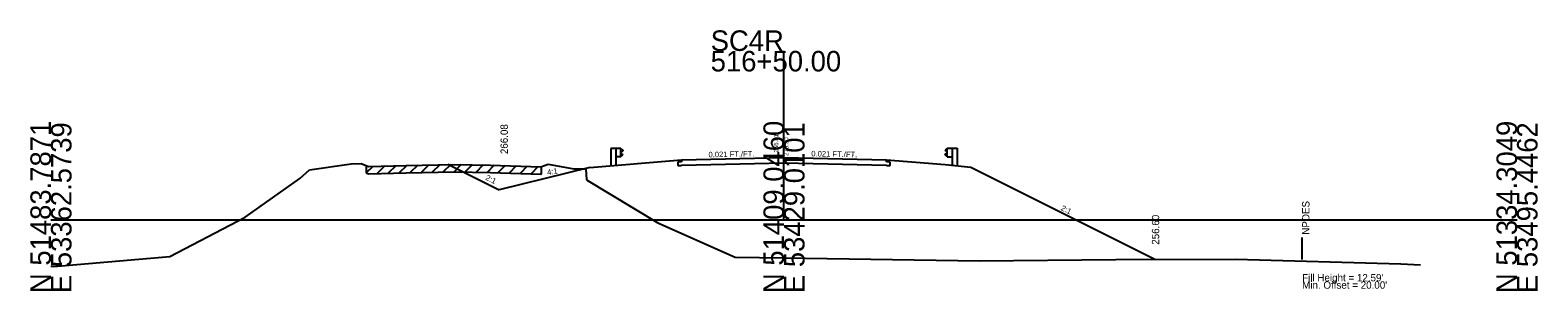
# Model space of a CAD drawing. Extents: x 7498 to 13027, y 90095 to 109625.
# Drawn here: x 8521.2 to 8726.8, y 106595.5 to 106631.1 of the extents above; entities that cross this region are included whole.
import ezdxf

# ---------------------------------------------------------------- set-up
doc = ezdxf.new("R2010")
doc.units = 0
for name, color, linetype in [('Level 10', 7, 'Continuous'), ('Level 11', 7, 'Continuous'), ('Level 12', 7, 'Continuous'), ('Level 24', 7, 'Continuous'), ('Level 32', 7, 'Continuous'), ('Level 33', 7, 'Continuous'), ('Level 50', 7, 'Continuous'), ('Level 55', 7, 'Continuous'), ('Level 59', 7, 'Continuous'), ('Level 6', 7, 'Continuous'), ('Level 60', 7, 'Continuous'), ('Level 61', 7, 'Continuous'), ('Level 63', 7, 'Continuous'), ('Level 7', 7, 'Continuous')]:
    doc.layers.add(name, color=color, linetype=linetype)

msp = doc.modelspace()

# ---------------------------------------------------------------- linework, layer by layer
at = {"layer": 'Level 11'}
for p, q in [((8609.99, 106613.07), (8609.49, 106613.05)), ((8609.49, 106613.05), (8609.49, 106612.57)), ((8609.99, 106613.37), (8609.99, 106613.07)), ((8637.99, 106613.07), (8637.99, 106613.37)), ((8638.49, 106613.05), (8637.99, 106613.07)), ((8638.49, 106612.57), (8638.49, 106613.05)), ((8609.49, 106612.57), (8609.99, 106612.59)), ((8637.99, 106612.59), (8638.49, 106612.57))]:
    msp.add_line(p, q, dxfattribs=at)
at = {"layer": 'Level 12'}
for p, q in [((8623.99, 106612.88), (8609.99, 106612.59)), ((8637.99, 106612.59), (8623.99, 106612.88))]:
    msp.add_line(p, q, dxfattribs=at)
at = {"layer": 'Level 24'}
for p, q in [((8600.38, 106614.92), (8600.38, 106612.51)), ((8601.05, 106614.92), (8600.38, 106614.92)), ((8601.72, 106614.92), (8601.05, 106614.92)), ((8601.05, 106614.92), (8601.05, 106612.57)), ((8601.72, 106613.75), (8601.05, 106613.75)), ((8601.72, 106613.75), (8601.72, 106614.92)), ((8601.72, 106614.85), (8601.99, 106614.65)), ((8601.99, 106614.6), (8601.72, 106614.4)), ((8601.99, 106614.07), (8601.72, 106614.27)), ((8601.72, 106613.82), (8601.99, 106614.02)), ((8601.99, 106614.65), (8601.99, 106614.6)), ((8601.99, 106614.02), (8601.99, 106614.07)), ((8646.26, 106614.88), (8645.99, 106614.68)), ((8645.99, 106614.68), (8645.99, 106614.63)), ((8645.99, 106614.63), (8646.26, 106614.43)), ((8645.99, 106614.1), (8646.26, 106614.3)), ((8645.99, 106614.05), (8645.99, 106614.1)), ((8646.26, 106613.85), (8645.99, 106614.05)), ((8646.26, 106613.78), (8646.26, 106614.95)), ((8646.26, 106614.95), (8646.93, 106614.95)), ((8646.26, 106613.78), (8646.93, 106613.78)), ((8646.93, 106614.95), (8646.93, 106612.6)), ((8646.93, 106614.95), (8647.6, 106614.95)), ((8647.6, 106614.95), (8647.6, 106612.54))]:
    msp.add_line(p, q, dxfattribs=at)
at = {"layer": 'Level 55'}
msp.add_line((8694.68, 106599.76), (8694.68, 106602.76), dxfattribs=at)
at = {"layer": 'Level 59'}
for p, q in [((8609.99, 106613.37), (8623.99, 106613.66)), ((8623.99, 106613.66), (8637.99, 106613.37))]:
    msp.add_line(p, q, dxfattribs=at)
at = {"layer": 'Level 6'}
for p, q in [((8597.49, 106612.32), (8609.99, 106613.37)), ((8637.99, 106613.37), (8645.99, 106612.7)), ((8645.99, 106612.7), (8649.49, 106612.35))]:
    msp.add_line(p, q, dxfattribs=at)
at = {"layer": 'Level 60'}
for p, q in [((8557.93, 106610.79), (8559.24, 106611.97)), ((8559.24, 106611.97), (8564.94, 106612.82)), ((8564.94, 106612.82), (8566.3, 106612.84)), ((8566.3, 106612.84), (8567.29, 106612.45)), ((8567.29, 106612.45), (8572.44, 106612.59)), ((8572.44, 106612.59), (8578.99, 106612.73)), ((8578.99, 106612.73), (8583.95, 106612.63)), ((8583.95, 106612.63), (8590.84, 106612.41)), ((8590.84, 106612.41), (8591.81, 106612.75)), ((8591.81, 106612.75), (8595.32, 106612.12)), ((8595.32, 106612.12), (8596.94, 106612.1)), ((8596.94, 106612.1), (8597.03, 106610.6)), ((8550.5, 106605.53), (8557.93, 106610.79)), ((8597.03, 106610.6), (8606.79, 106604.74)), ((8540.19, 106600.16), (8550.5, 106605.53)), ((8606.79, 106604.74), (8617.33, 106600.07)), ((8523.99, 106598.83), (8524.88, 106598.85)), ((8524.88, 106598.85), (8540.19, 106600.16)), ((8617.33, 106600.07), (8623.99, 106599.97)), ((8623.99, 106599.97), (8650.65, 106599.56)), ((8650.65, 106599.56), (8669.28, 106599.73)), ((8669.28, 106599.73), (8685.62, 106599.81)), ((8685.62, 106599.81), (8708.12, 106599.16)), ((8708.12, 106599.16), (8710.83, 106599))]:
    msp.add_line(p, q, dxfattribs=at)
at = {"layer": 'Level 61'}
for p, q in [((8566.99, 106612.56), (8566.99, 106611.56)), ((8567.89, 106612.46), (8566.99, 106611.56)), ((8566.99, 106611.56), (8567.29, 106611.45)), ((8567.29, 106611.45), (8572.44, 106611.59)), ((8569.52, 106612.51), (8568.49, 106611.48)), ((8571.02, 106612.55), (8569.99, 106611.52)), ((8572.52, 106612.59), (8571.49, 106611.56)), ((8572.44, 106611.59), (8578.99, 106611.73)), ((8574.02, 106612.62), (8572.99, 106611.6)), ((8575.52, 106612.66), (8574.49, 106611.63)), ((8577.02, 106612.69), (8575.99, 106611.67)), ((8578.52, 106612.72), (8577.49, 106611.7)), ((8579.97, 106612.71), (8578.99, 106611.73)), ((8578.99, 106611.73), (8583.95, 106611.63)), ((8581.47, 106612.68), (8580.49, 106611.7)), ((8582.97, 106612.65), (8581.99, 106611.67)), ((8584.47, 106612.62), (8583.49, 106611.64)), ((8583.95, 106611.63), (8590.84, 106611.41)), ((8585.96, 106612.57), (8584.99, 106611.6)), ((8587.46, 106612.52), (8586.49, 106611.55)), ((8588.96, 106612.47), (8587.99, 106611.5)), ((8590.46, 106612.42), (8589.49, 106611.45)), ((8590.84, 106611.41), (8590.93, 106611.44)), ((8590.93, 106611.44), (8590.93, 106612.44))]:
    msp.add_line(p, q, dxfattribs=at)
at = {"layer": 'Level 63'}
for p, q in [((8623.99, 106605.16), (8623.99, 106628.22)), ((8523.99, 106605.16), (8623.99, 106605.16)), ((8623.99, 106605.16), (8723.99, 106605.16))]:
    msp.add_line(p, q, dxfattribs=at)
at = {"layer": 'Level 7'}
for p, q in [((8578.13, 106612.75), (8585.15, 106609.24)), ((8597.49, 106612.32), (8585.15, 106609.24)), ((8649.49, 106612.35), (8674.68, 106599.76))]:
    msp.add_line(p, q, dxfattribs=at)

# ---------------------------------------------------------------- texts
at = {"layer": 'Level 10'}
msp.add_text('256.81', height=0.6, rotation=90, dxfattribs=at).set_placement((8623.21, 106614.34))
at = {"layer": 'Level 32'}
for s, rotation, p in [('0.021 FT./FT.', 1.1916, (8613.7, 106613.69)), ('0.021 FT./FT.', 358.8084, (8627.71, 106613.83)), ('2:1', 333.435, (8583.21, 106610.67)), ('4:1', 9.4623, (8591.74, 106611.26)), ('2:1', 333.435, (8661.69, 106606.53))]:
    msp.add_text(s, height=0.75, rotation=rotation, dxfattribs=at).set_placement(p)
at = {"layer": 'Level 33'}
for s, p in [('266.08', (8586.32, 106614.13)), ('256.60', (8675.18, 106601.76))]:
    msp.add_text(s, height=1, rotation=90, dxfattribs=at).set_placement(p)
at = {"layer": 'Level 50'}
msp.add_text(' NPDES', height=1, rotation=90, dxfattribs=at).set_placement((8695.68, 106602.76))
for s, p in [("Fill Height = 12.59' ", (8694.68, 106596.76)), ("Min. Offset = 20.00' ", (8694.68, 106595.76))]:
    msp.add_text(s, height=1, dxfattribs=at).set_placement(p)
at = {"layer": 'Level 59'}
msp.add_text(' 270.50', height=0.6, rotation=90, dxfattribs=at).set_placement((8624.59, 106613.66))
at = {"layer": 'Level 63'}
for s, p in [('SC4R', (8613.99, 106628.22)), ('516+50.00', (8613.99, 106625.42))]:
    msp.add_text(s, height=2.8, dxfattribs=at).set_placement(p)
for s, p in [('N 51483.7871', (8523.99, 106595.16)), ('E 53362.5739', (8526.79, 106595.16)), ('N 51409.0460', (8623.99, 106595.16)), ('E 53429.0101', (8626.79, 106595.16)), ('N 51334.3049', (8723.99, 106595.16)), ('E 53495.4462', (8726.79, 106595.16))]:
    msp.add_text(s, height=2.8, rotation=90, dxfattribs=at).set_placement(p)

doc.saveas('drawing.dxf')
